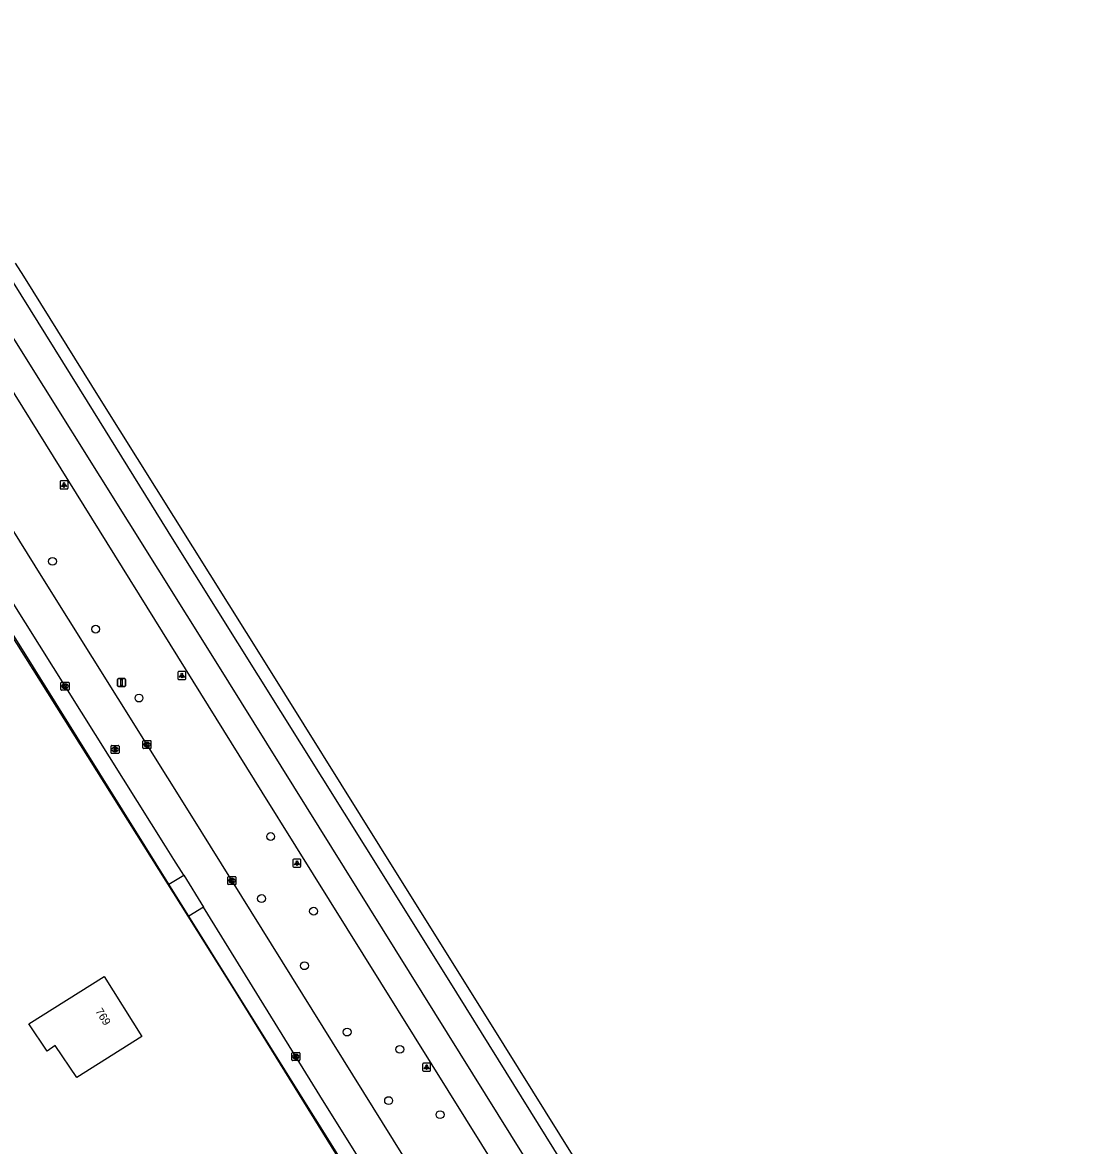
# Model space of a CAD drawing. Extents: x 158132 to 159658, y 385257 to 387209.
# Drawn here: x 159234.9 to 159366.9, y 386462.6 to 386602.9 of the extents above; entities that cross this region are included whole.
import ezdxf

# ---------------------------------------------------------------- set-up
doc = ezdxf.new("R2010")
doc.units = 0
for name, color, linetype in [('IMGEO_Boom', 7, 'Continuous'), ('IMGEO_Hek', 7, 'Continuous'), ('IMGEO_Kolk', 7, 'Continuous'), ('IMGEO_Lichtpunt', 7, 'Continuous'), ('IMGEO_Pand', 7, 'Continuous'), ('IMGEO_Pand_nummerreeks', 7, 'Continuous'), ('IMGEO_Rijbaan_lokaal_open', 7, 'Continuous'), ('IMGEO_Rijbaan_regionaal_gesloten', 7, 'Continuous'), ('IMGEO_Rioolput', 7, 'Continuous'), ('IMGEO_Verkeersbordpaal', 7, 'Continuous'), ('IMGEO_Voetpad_open', 7, 'Continuous')]:
    doc.layers.add(name, color=color, linetype=linetype)

msp = doc.modelspace()

# ---------------------------------------------------------------- linework, layer by layer
at = {"layer": 'IMGEO_Boom'}
for centre in [(159238.6, 386535.58), (159243.99, 386527.11), (159249.41, 386518.5), (159265.85, 386501.2), (159264.71, 386493.45), (159271.21, 386491.87), (159270.07, 386485.06), (159275.4, 386476.77), (159281.98, 386474.61), (159280.58, 386468.21), (159287.01, 386466.45)]:
    msp.add_circle(centre, 0.489, dxfattribs=at)
at = {"layer": 'IMGEO_Hek'}
for points in [[(159250.06, 386500), (159194.34, 386588.63), (159192.21, 386592.03)], [(159278.19, 386454.83), (159261.26, 386482.17), (159250.06, 386500)]]:
    msp.add_lwpolyline(points, dxfattribs=at)
at = {"layer": 'IMGEO_Kolk'}
for p, q in [((159239.66, 386519.56), (159239.66, 386520.41)), ((159239.74, 386520.49), (159240.59, 386520.49)), ((159240.15, 386520.26), (159240.18, 386520.26)), ((159240.67, 386520.41), (159240.67, 386519.56)), ((159240.59, 386519.48), (159239.74, 386519.48)), ((159240.17, 386519.71), (159240.15, 386519.71)), ((159249.9, 386512.27), (159249.9, 386513.12)), ((159249.98, 386513.19), (159250.83, 386513.19)), ((159250.9, 386513.12), (159250.9, 386512.27)), ((159250.83, 386512.19), (159249.98, 386512.19)), ((159250.39, 386512.97), (159250.41, 386512.97)), ((159250.41, 386512.41), (159250.39, 386512.41)), ((159260.59, 386496.19), (159261.44, 386496.19)), ((159260.52, 386495.26), (159260.52, 386496.12)), ((159261.44, 386495.19), (159260.59, 386495.19)), ((159261, 386495.97), (159261.03, 386495.97)), ((159261.03, 386495.41), (159261, 386495.41)), ((159261.52, 386496.12), (159261.52, 386495.26)), ((159268.49, 386473.29), (159268.49, 386474.14)), ((159268.57, 386474.22), (159269.42, 386474.22)), ((159268.98, 386473.99), (159269, 386473.99)), ((159269.49, 386474.14), (159269.49, 386473.29)), ((159269.42, 386473.21), (159268.57, 386473.21)), ((159269, 386473.44), (159268.98, 386473.44))]:
    msp.add_line(p, q, dxfattribs=at)
for points in [[(159239.66, 386519.56), (159239.66, 386520.41)], [(159239.74, 386520.49), (159240.59, 386520.49)], [(159239.98, 386520.18), (159240.11, 386520.18), (159240.11, 386520.03), (159240.24, 386520.18), (159240.4, 386520.18), (159240.26, 386520.03), (159240.41, 386519.78), (159240.26, 386519.78), (159240.17, 386519.95), (159240.11, 386519.88), (159240.11, 386519.78), (159239.98, 386519.78), (159239.98, 386520.18)], [(159240.67, 386520.41), (159240.67, 386519.56)], [(159240.59, 386519.48), (159239.74, 386519.48)], [(159249.9, 386512.27), (159249.9, 386513.12)], [(159249.98, 386513.19), (159250.83, 386513.19)], [(159250.9, 386513.12), (159250.9, 386512.27)], [(159250.83, 386512.19), (159249.98, 386512.19)], [(159250.22, 386512.89), (159250.35, 386512.89), (159250.35, 386512.74), (159250.47, 386512.89), (159250.64, 386512.89), (159250.49, 386512.74), (159250.65, 386512.49), (159250.49, 386512.49), (159250.41, 386512.66), (159250.35, 386512.59), (159250.35, 386512.49), (159250.22, 386512.49), (159250.22, 386512.89)], [(159260.59, 386496.19), (159261.44, 386496.19)], [(159260.52, 386495.26), (159260.52, 386496.12)], [(159261.44, 386495.19), (159260.59, 386495.19)], [(159260.84, 386495.89), (159260.96, 386495.89), (159260.96, 386495.74), (159261.09, 386495.89), (159261.25, 386495.89), (159261.11, 386495.74), (159261.26, 386495.49), (159261.11, 386495.49), (159261.02, 386495.65), (159260.96, 386495.59), (159260.96, 386495.49), (159260.84, 386495.49), (159260.84, 386495.89)], [(159261.52, 386496.12), (159261.52, 386495.26)], [(159268.49, 386473.29), (159268.49, 386474.14)], [(159268.57, 386474.22), (159269.42, 386474.22)], [(159268.81, 386473.91), (159268.94, 386473.91), (159268.94, 386473.76), (159269.06, 386473.91), (159269.23, 386473.91), (159269.08, 386473.76), (159269.24, 386473.51), (159269.08, 386473.51), (159269, 386473.68), (159268.94, 386473.61), (159268.94, 386473.51), (159268.81, 386473.51), (159268.81, 386473.91)], [(159269.49, 386474.14), (159269.49, 386473.29)], [(159269.42, 386473.21), (159268.57, 386473.21)]]:
    msp.add_lwpolyline(points, dxfattribs=at)
for centre, start, end in [((159239.74, 386520.41), 91.552, 178.448), ((159239.74, 386520.41), 91.552, 178.448), ((159240.59, 386520.41), 1.552, 88.448), ((159240.59, 386520.41), 1.552, 88.448), ((159239.74, 386519.56), 181.552, 268.448), ((159239.74, 386519.56), 181.552, 268.448), ((159240.59, 386519.56), 271.552, 358.448), ((159240.59, 386519.56), 271.552, 358.448), ((159249.98, 386513.12), 91.552, 178.448), ((159249.98, 386513.12), 91.552, 178.448), ((159250.83, 386513.12), 1.552, 88.448), ((159250.83, 386513.12), 1.552, 88.448), ((159249.98, 386512.27), 181.552, 268.448), ((159249.98, 386512.27), 181.552, 268.448), ((159250.83, 386512.27), 271.552, 358.448), ((159250.83, 386512.27), 271.552, 358.448), ((159260.59, 386496.11), 91.552, 178.448), ((159260.59, 386496.11), 91.552, 178.448), ((159261.44, 386496.11), 1.552, 88.448), ((159261.44, 386496.11), 1.552, 88.448), ((159260.59, 386495.26), 181.552, 268.448), ((159260.59, 386495.26), 181.552, 268.448), ((159261.44, 386495.26), 271.552, 358.448), ((159261.44, 386495.26), 271.552, 358.448), ((159268.57, 386474.14), 91.552, 178.448), ((159268.57, 386474.14), 91.552, 178.448), ((159269.42, 386474.14), 1.552, 88.448), ((159269.42, 386474.14), 1.552, 88.448), ((159268.57, 386473.29), 181.552, 268.448), ((159268.57, 386473.29), 181.552, 268.448), ((159269.42, 386473.29), 271.552, 358.448), ((159269.42, 386473.29), 271.552, 358.448)]:
    msp.add_arc(centre, 0.0765, start, end, dxfattribs=at)
for centre, major_axis, ratio, start_param, end_param in [((159240.15, 386519.98), (-0.387, 0.002), 0.722429, 4.712389, 7.853982), ((159240.18, 386519.98), (-0.39, 0.002), 0.717154, 1.570796, 4.712389), ((159250.39, 386512.69), (-0.387, 0.002), 0.722429, 4.712389, 7.853982), ((159250.41, 386512.69), (-0.39, 0.002), 0.717154, 1.570796, 4.712389), ((159261, 386495.69), (-0.387, 0.002), 0.722429, 4.712389, 7.853982), ((159261.03, 386495.69), (-0.39, 0.002), 0.717154, 1.570796, 4.712389), ((159268.98, 386473.71), (-0.387, 0.002), 0.722429, 4.712389, 7.853982), ((159269, 386473.71), (-0.39, 0.002), 0.717154, 1.570796, 4.712389)]:
    msp.add_ellipse(centre, major_axis=major_axis, ratio=ratio, start_param=start_param, end_param=end_param, dxfattribs=at)
at = {"layer": 'IMGEO_Lichtpunt'}
for p, q in [((159239.54, 386545.54), (159239.54, 386544.73)), ((159239.54, 386545.54), (159239.54, 386544.73)), ((159240.44, 386545.63), (159239.64, 386545.63)), ((159240.44, 386545.63), (159239.64, 386545.63)), ((159240.54, 386544.73), (159240.54, 386545.54)), ((159240.54, 386544.73), (159240.54, 386545.54)), ((159239.64, 386544.64), (159240.44, 386544.64)), ((159239.64, 386544.64), (159240.44, 386544.64)), ((159254.26, 386521.71), (159254.26, 386520.91)), ((159254.26, 386521.71), (159254.26, 386520.91)), ((159255.16, 386521.81), (159254.35, 386521.81)), ((159255.16, 386521.81), (159254.35, 386521.81)), ((159255.26, 386520.91), (159255.26, 386521.71)), ((159255.26, 386520.91), (159255.26, 386521.71)), ((159254.35, 386520.81), (159255.16, 386520.81)), ((159254.35, 386520.81), (159255.16, 386520.81)), ((159268.63, 386498.28), (159268.63, 386497.48)), ((159268.63, 386498.28), (159268.63, 386497.48)), ((159269.53, 386498.38), (159268.73, 386498.38)), ((159269.53, 386498.38), (159268.73, 386498.38)), ((159269.63, 386497.48), (159269.63, 386498.28)), ((159269.63, 386497.48), (159269.63, 386498.28)), ((159268.73, 386497.38), (159269.53, 386497.38)), ((159268.73, 386497.38), (159269.53, 386497.38)), ((159284.83, 386472.79), (159284.83, 386471.98)), ((159284.83, 386472.79), (159284.83, 386471.98)), ((159285.73, 386472.88), (159284.93, 386472.88)), ((159285.73, 386472.88), (159284.93, 386472.88)), ((159285.83, 386471.98), (159285.83, 386472.79)), ((159285.83, 386471.98), (159285.83, 386472.79)), ((159284.93, 386471.89), (159285.73, 386471.89)), ((159284.93, 386471.89), (159285.73, 386471.89))]:
    msp.add_line(p, q, dxfattribs=at)
for points in [[(159239.92, 386545.2), (159239.96, 386545.17), (159239.77, 386544.91), (159239.73, 386544.94), (159239.92, 386545.2)], [(159240.02, 386545.15), (159240.07, 386545.15), (159240.07, 386544.83), (159240.02, 386544.83), (159240.02, 386545.15)], [(159240.13, 386545.17), (159240.17, 386545.2), (159240.35, 386544.94), (159240.32, 386544.91), (159240.13, 386545.17)], [(159254.63, 386521.38), (159254.67, 386521.35), (159254.49, 386521.09), (159254.45, 386521.11), (159254.63, 386521.38)], [(159254.74, 386521.33), (159254.78, 386521.33), (159254.78, 386521.01), (159254.74, 386521.01), (159254.74, 386521.33)], [(159254.85, 386521.35), (159254.88, 386521.38), (159255.07, 386521.11), (159255.03, 386521.09), (159254.85, 386521.35)], [(159269.01, 386497.95), (159269.04, 386497.92), (159268.86, 386497.66), (159268.82, 386497.68), (159269.01, 386497.95)], [(159269.11, 386497.9), (159269.15, 386497.9), (159269.15, 386497.58), (159269.11, 386497.58), (159269.11, 386497.9)], [(159269.22, 386497.92), (159269.26, 386497.95), (159269.44, 386497.68), (159269.4, 386497.66), (159269.22, 386497.92)], [(159285.21, 386472.45), (159285.24, 386472.42), (159285.06, 386472.16), (159285.02, 386472.19), (159285.21, 386472.45)], [(159285.31, 386472.4), (159285.35, 386472.4), (159285.35, 386472.08), (159285.31, 386472.08), (159285.31, 386472.4)], [(159285.42, 386472.42), (159285.46, 386472.45), (159285.64, 386472.19), (159285.6, 386472.16), (159285.42, 386472.42)]]:
    msp.add_lwpolyline(points, dxfattribs=at)
for centre in [(159240.04, 386545.34), (159254.76, 386521.51), (159269.13, 386498.08), (159285.33, 386472.59)]:
    msp.add_circle(centre, 0.0994, dxfattribs=at)
for centre, start, end in [((159239.64, 386545.54), 90, 180), ((159239.64, 386545.54), 90, 180), ((159240.44, 386545.54), 0, 90), ((159240.44, 386545.54), 0, 90), ((159239.64, 386544.73), 180, 270), ((159239.64, 386544.73), 180, 270), ((159240.44, 386544.73), 270, 0), ((159240.44, 386544.73), 270, 360), ((159254.35, 386521.71), 90, 180), ((159254.35, 386521.71), 90, 180), ((159255.16, 386521.71), 0, 90), ((159255.16, 386521.71), 0, 90), ((159254.35, 386520.91), 180, 270), ((159254.35, 386520.91), 180, 270), ((159255.16, 386520.91), 270, 0), ((159255.16, 386520.91), 270, 360), ((159268.73, 386498.28), 90, 180), ((159268.73, 386498.28), 90, 180), ((159269.53, 386498.28), 0, 90), ((159269.53, 386498.28), 0, 90), ((159268.73, 386497.48), 180, 270), ((159268.73, 386497.48), 180, 270), ((159269.53, 386497.48), 270, 0), ((159269.53, 386497.48), 270, 360), ((159284.93, 386472.79), 90, 180), ((159284.93, 386472.79), 90, 180), ((159285.73, 386472.79), 0, 90), ((159285.73, 386472.79), 0, 90), ((159284.93, 386471.98), 180, 270), ((159284.93, 386471.98), 180, 270), ((159285.73, 386471.98), 270, 0), ((159285.73, 386471.98), 270, 360)]:
    msp.add_arc(centre, 0.0946, start, end, dxfattribs=at)
at = {"layer": 'IMGEO_Pand'}
msp.add_lwpolyline([(159237.93, 386474.4), (159235.65, 386477.8), (159245.05, 386483.72), (159249.78, 386476.2), (159241.64, 386471.08), (159238.95, 386475.09), (159237.93, 386474.4)], dxfattribs=at)
at = {"layer": 'IMGEO_Rijbaan_lokaal_open'}
for points in [[(159255, 386496.36), (159253.77, 386498.34), (159252.73, 386500), (159231.68, 386533.49), (159209.62, 386568.89), (159197.67, 386587.77), (159196.24, 386590.04), (159191.93, 386597.03), (159189.83, 386600.39), (159188.27, 386602.91)], [(159298.35, 386435.69), (159274.93, 386473.31), (159258.34, 386500), (159256.22, 386503.4), (159237.38, 386533.49), (159217.04, 386566.17)], [(159255, 386496.36), (159257.46, 386492.38)], [(159368.42, 386314.26), (159342.27, 386356.54), (159336.87, 386365.14), (159318.51, 386394.36), (159300.96, 386422.44), (159295.37, 386431.39), (159272.54, 386467.97), (159257.46, 386492.38)]]:
    msp.add_lwpolyline(points, dxfattribs=at)
at = {"layer": 'IMGEO_Rijbaan_regionaal_gesloten'}
for points in [[(159337.59, 386396.88), (159259.04, 386523.03), (159222.99, 386580.57)], [(159334.62, 386395.01), (159326.35, 386408.09), (159320.18, 386417.89), (159312.88, 386429.61), (159302.23, 386446.71), (159294.43, 386459.19), (159268.99, 386500), (159264.8, 386506.73), (159232.99, 386557.93), (159230.94, 386561.23), (159229.11, 386564.24), (159222.73, 386574.37), (159219.83, 386578.66)], [(159232.64, 386572.02), (159233.68, 386570.42), (159242.94, 386555.56), (159253.77, 386538.11), (159277.62, 386500), (159288.12, 386483.23), (159318.51, 386434.33), (159340.68, 386398.8)], [(159233.96, 386572.84), (159234.98, 386571.21), (159244.66, 386555.67), (159265.17, 386522.91), (159279.46, 386500), (159294.97, 386475.13), (159326.37, 386424.73), (159342.02, 386399.64)]]:
    msp.add_lwpolyline(points, dxfattribs=at)
at = {"layer": 'IMGEO_Rioolput'}
for p, q in [((159245.91, 386511.66), (159245.91, 386512.51)), ((159245.98, 386512.59), (159246.84, 386512.59)), ((159246.4, 386512.36), (159246.42, 386512.36)), ((159246.42, 386511.81), (159246.4, 386511.81)), ((159246.91, 386512.51), (159246.91, 386511.66)), ((159246.84, 386511.58), (159245.98, 386511.58))]:
    msp.add_line(p, q, dxfattribs=at)
for points in [[(159245.91, 386511.66), (159245.91, 386512.51)], [(159245.98, 386512.59), (159246.84, 386512.59)], [(159246.5, 386512.28), (159246.25, 386512.28), (159246.25, 386511.88)], [(159246.25, 386511.88), (159246.37, 386511.88), (159246.37, 386512.05), (159246.38, 386512.05)], [(159246.43, 386512.2), (159246.37, 386512.2), (159246.37, 386512.12)], [(159246.37, 386512.12), (159246.42, 386512.12)], [(159246.43, 386512.02), (159246.5, 386511.88), (159246.64, 386511.88), (159246.57, 386512.01)], [(159246.91, 386512.51), (159246.91, 386511.66)], [(159246.84, 386511.58), (159245.98, 386511.58)]]:
    msp.add_lwpolyline(points, dxfattribs=at)
for centre, radius, start, end in [((159245.99, 386512.51), 0.0765, 91.552, 178.448), ((159245.99, 386512.51), 0.0765, 91.552, 178.448), ((159245.99, 386511.66), 0.0765, 181.552, 268.448), ((159245.99, 386511.66), 0.0765, 181.552, 268.448), ((159246.38, 386511.99), 0.0533, 26.0293, 88.6989), ((159246.41, 386512.31), 0.19, 274.7715, 282.9687), ((159246.43, 386512.11), 0.0964, 77.0061, 93.1865), ((159246.45, 386512.16), 0.0378, 276.6634, 79.6772), ((159246.5, 386512.17), 0.109, 350.3612, 89.416), ((159246.5, 386512.17), 0.112, 277.5842, 350.9817), ((159246.48, 386511.96), 0.108, 29.5134, 73.7905), ((159246.83, 386512.51), 0.0765, 1.552, 88.448), ((159246.83, 386512.51), 0.0765, 1.552, 88.448), ((159246.83, 386511.66), 0.0765, 271.552, 358.448), ((159246.83, 386511.66), 0.0765, 271.552, 358.448)]:
    msp.add_arc(centre, radius, start, end, dxfattribs=at)
for centre, major_axis, ratio, start_param, end_param in [((159246.4, 386512.08), (-0.387, 0.002), 0.722429, 4.712389, 7.853982), ((159246.42, 386512.08), (-0.39, 0.002), 0.717154, 1.570796, 4.712389)]:
    msp.add_ellipse(centre, major_axis=major_axis, ratio=ratio, start_param=start_param, end_param=end_param, dxfattribs=at)
at = {"layer": 'IMGEO_Verkeersbordpaal'}
for p, q in [((159246.73, 386520.04), (159246.73, 386520.84)), ((159246.73, 386520.84), (159246.73, 386520.04)), ((159246.83, 386520.94), (159247.62, 386520.94)), ((159247.62, 386520.94), (159246.83, 386520.94)), ((159247.72, 386520.84), (159247.72, 386520.04)), ((159247.72, 386520.04), (159247.72, 386520.84)), ((159247.62, 386519.94), (159246.83, 386519.94)), ((159246.83, 386519.94), (159247.62, 386519.94))]:
    msp.add_line(p, q, dxfattribs=at)
msp.add_lwpolyline([(159247.15, 386520.81), (159247.3, 386520.81), (159247.3, 386520.06), (159247.15, 386520.06), (159247.15, 386520.81)], dxfattribs=at)
for centre, start, end in [((159246.83, 386520.84), 90, 180), ((159246.83, 386520.84), 90, 180), ((159246.83, 386520.04), 180, 270), ((159246.83, 386520.04), 180, 270), ((159247.62, 386520.84), 0, 90), ((159247.62, 386520.84), 360, 90), ((159247.62, 386520.04), 270, 0), ((159247.62, 386520.04), 270, 0)]:
    msp.add_arc(centre, 0.1, start, end, dxfattribs=at)
at = {"layer": 'IMGEO_Voetpad_open'}
for points in [[(159253.15, 386495.23), (159250.17, 386500), (159194.12, 386589.79), (159192.73, 386592.19)], [(159253.15, 386495.23), (159255, 386496.36)], [(159255.64, 386491.24), (159253.15, 386495.23)], [(159257.46, 386492.38), (159255.64, 386491.24)], [(159565.37, 385995.91), (159562.79, 386000), (159562.61, 386000.29), (159500, 386100.31), (159430.86, 386210.85), (159406.37, 386250), (159377.74, 386296.22), (159335.56, 386363.38), (159320.93, 386386.67), (159299.26, 386421.42), (159282.86, 386447.72), (159281.62, 386449.7), (159261.29, 386482.19), (159255.64, 386491.24)]]:
    msp.add_lwpolyline(points, dxfattribs=at)

# ---------------------------------------------------------------- texts
at = {"layer": 'IMGEO_Pand_nummerreeks'}
msp.add_text('769', height=1, rotation=302.1976, dxfattribs=at).set_placement((159243.91, 386479.38))

doc.saveas('drawing.dxf')
